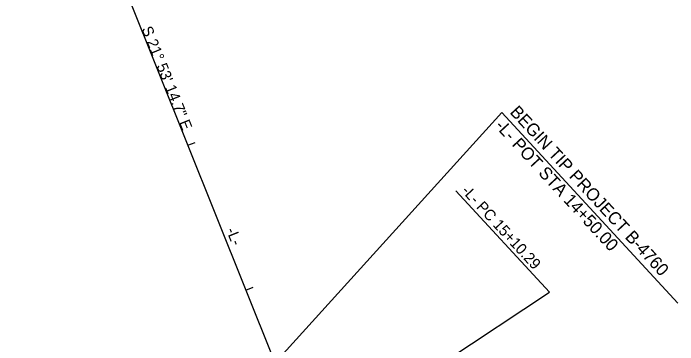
# Model space of a CAD drawing. Extents: x 1702862 to 1704514, y 793768 to 796215.
# Drawn here: x 1702863.3 to 1703289.2, y 795692.8 to 795905.1 of the extents above; entities that cross this region are included whole.
import ezdxf

# ---------------------------------------------------------------- set-up
doc = ezdxf.new("R2010")
doc.units = 0
for name, color, linetype in [('Prop DSN Text', 7, 'Continuous'), ('Prop Horizontal Alignment', 7, 'Continuous'), ('Prop Horizontal Alignment Direction Label', 7, 'Continuous'), ('Prop Horizontal Alignment Station Label', 7, 'Continuous'), ('Prop Horizontal Alignment Tick Small', 7, 'Continuous'), ('Prop Leader Line Medium', 7, 'Continuous')]:
    doc.layers.add(name, color=color, linetype=linetype)

msp = doc.modelspace()

# ---------------------------------------------------------------- linework, layer by layer
at = {"layer": 'Prop Horizontal Alignment'}
msp.add_line((1702863.33, 796098.94), (1703053.56, 795625.43), dxfattribs=at)
at = {"layer": 'Prop Horizontal Alignment Station Label'}
for p, q in [((1703206.95, 795726.48), (1703147.05, 795791.36)), ((1703054.96, 795625.99), (1703206.95, 795726.48))]:
    msp.add_line(p, q, dxfattribs=at)
at = {"layer": 'Prop Horizontal Alignment Tick Small'}
for p, q in [((1702975.17, 795820.57), (1702979.81, 795822.43)), ((1703012.45, 795727.78), (1703017.09, 795729.64))]:
    msp.add_line(p, q, dxfattribs=at)
at = {"layer": 'Prop Leader Line Medium'}
for q in [(1703031.09, 795681.38), (1703289.22, 795719.39)]:
    msp.add_line((1703176.52, 795841.48), q, dxfattribs=at)

# ---------------------------------------------------------------- texts
at = {"layer": 'Prop DSN Text'}
for s, p in [('BEGIN TIP PROJECT B-4760', (1703181.19, 795841.4)), ('-L- POT STA 14+50.00', (1703171.64, 795832.58))]:
    msp.add_text(s, height=8, rotation=312.7091, dxfattribs=at).set_placement(p)
at = {"layer": 'Prop Horizontal Alignment Direction Label'}
for s, p in [('S 21%%d 53\' 14.7" E', (1702945.43, 795895.14)), ('-L-', (1702999.63, 795766.3))]:
    msp.add_text(s, height=7, rotation=291.8874, dxfattribs=at).set_placement(p)
at = {"layer": 'Prop Horizontal Alignment Station Label'}
msp.add_text('-L- PC 15+10.29', height=7, rotation=312.7091, dxfattribs=at).set_placement((1703150.21, 795791.05))

doc.saveas('drawing.dxf')
